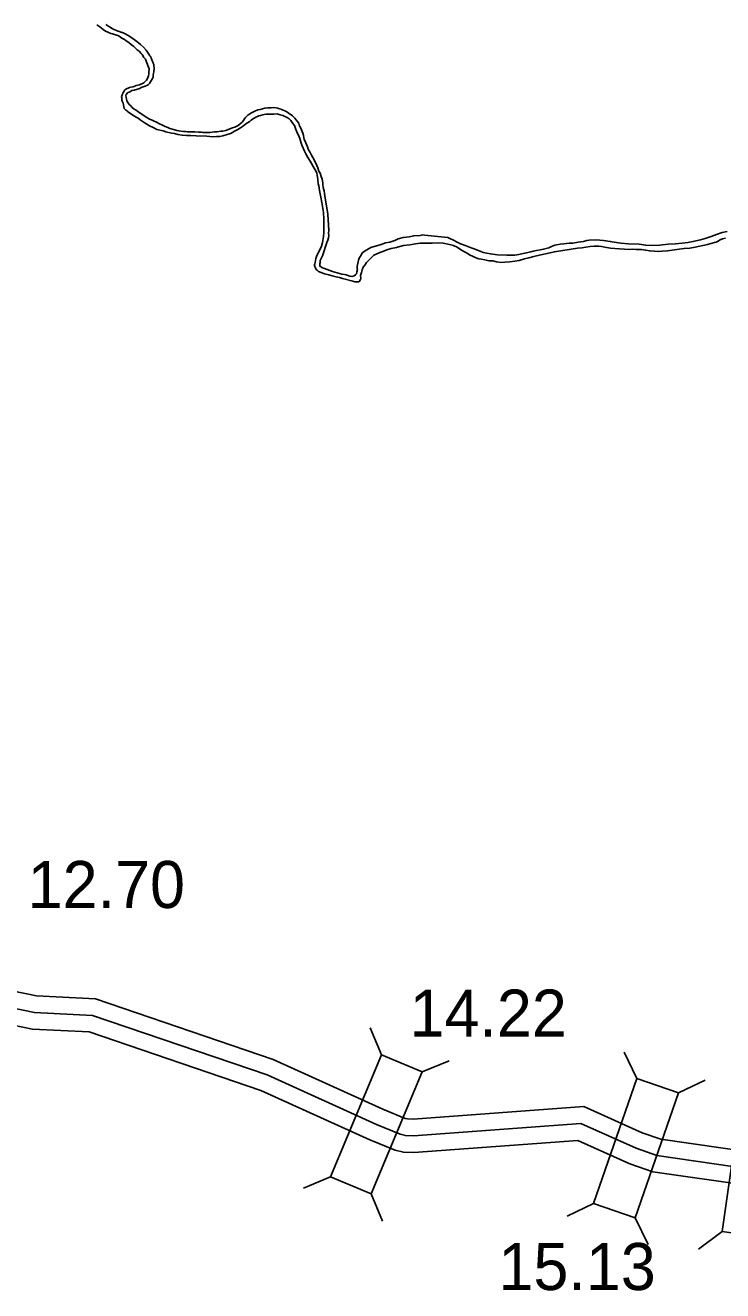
# Model space of a CAD drawing. Extents: x -83719 to 153526, y -11835 to 11446.
# Drawn here: x -2247.8 to -2038.9, y -454.1 to -75.2 of the extents above; entities that cross this region are included whole.
import ezdxf

# ---------------------------------------------------------------- set-up
doc = ezdxf.new("R2010")
doc.units = 0
for name, color, linetype in [('Level 10', 7, 'Continuous'), ('Level 20', 7, 'Continuous'), ('Level 25', 7, 'Continuous'), ('Level 58', 7, 'Continuous'), ('Level 59', 7, 'Continuous'), ('Level 9', 7, 'Continuous')]:
    doc.layers.add(name, color=color, linetype=linetype)

msp = doc.modelspace()

# ---------------------------------------------------------------- linework, layer by layer
at = {"layer": 'Level 10'}
for points in [[(-2375.71, -339.39), (-2328.82, -347.97), (-2266.83, -361.19), (-2244.37, -365.84), (-2226.7, -366.69), (-2173.53, -384.83), (-2140.64, -399.71), (-2134, -402.48), (-2133.29, -402.64), (-2131.62, -402.69), (-2080.47, -398.94), (-2063, -406.77), (-2057.47, -408.69), (-2029.08, -412.8), (-1988.92, -417.96), (-1987.26, -417.72), (-1985.49, -417.1), (-1983.44, -416.15), (-1964.63, -407.71), (-1915.1, -385.32), (-1891.4, -374.85)], [(-2379.18, -348.92), (-2330.76, -357.78), (-2268.89, -370.97), (-2245.63, -375.79), (-2228.59, -376.61), (-2177.21, -394.14), (-2144.62, -408.89), (-2137.04, -412.05), (-2134.54, -412.61), (-2131.41, -412.7), (-2082.26, -409.1), (-2066.69, -416.07), (-2059.85, -418.45), (-2030.43, -422.71), (-1988.85, -428.05), (-1984.86, -427.48), (-1981.74, -426.37), (-1979.31, -425.26), (-1960.53, -416.83), (-1911.02, -394.45), (-1887.36, -383.99)]]:
    msp.add_lwpolyline(points, dxfattribs=at)
at = {"layer": 'Level 20'}
for p, q in [((-2141.1, -383.49), (-2144.45, -375.35)), ((-2064.58, -390.55), (-2068.42, -382.63)), ((-2128.92, -388.56), (-2120.78, -385.22)), ((-2052.11, -394.89), (-2044.19, -391.05)), ((-2156.34, -420.04), (-2164.48, -423.39)), ((-2144.16, -425.12), (-2140.81, -433.25)), ((-2077.58, -427.96), (-2085.5, -431.79)), ((-2065.11, -432.29), (-2061.28, -440.21)), ((-2039.12, -436.41), (-2046.17, -441.67))]:
    msp.add_line(p, q, dxfattribs=at)
for points in [[(-2144.16, -425.12), (-2128.92, -388.56), (-2141.1, -383.49), (-2156.34, -420.04)], [(-2065.11, -432.29), (-2052.11, -394.89), (-2064.58, -390.55), (-2077.58, -427.96)], [(-2033.45, -397.21), (-2039.12, -436.41), (-2026.06, -438.3), (-2020.38, -399.1)]]:
    msp.add_lwpolyline(points, close=True, dxfattribs=at)
at = {"layer": 'Level 59'}
msp.add_lwpolyline([(-2267.86, -366.08), (-2245, -370.82), (-2227.65, -371.65), (-2175.37, -389.48), (-2142.63, -404.3), (-2135.52, -407.26), (-2133.91, -407.62), (-2131.51, -407.7), (-2081.36, -404.02), (-2064.85, -411.42), (-2058.66, -413.57), (-2029.75, -417.76), (-1988.88, -423.01), (-1986.06, -422.6), (-1983.61, -421.73), (-1981.37, -420.71), (-1962.58, -412.27), (-1913.06, -389.88), (-1889.38, -379.42)], dxfattribs=at)
at = {"layer": 'Level 9'}
for points in [[(-2215.06, -102.35), (-2217.02, -101.09), (-2217.19, -100.93), (-2217.77, -100.44), (-2218.11, -100.09), (-2218.26, -99.62), (-2218.31, -98.99), (-2218.49, -98.49), (-2218.59, -98.26), (-2218.73, -97.93), (-2218.81, -97.63), (-2218.85, -97.4), (-2218.89, -96.93), (-2218.93, -96.59), (-2218.87, -96.33), (-2218.78, -96.02), (-2218.69, -95.85), (-2218.5, -95.45), (-2218.3, -95.17), (-2218.08, -94.67), (-2217.95, -94.53), (-2217.66, -94.26), (-2216.54, -93.76), (-2216.2, -93.72), (-2215.44, -93.56), (-2214.55, -93.24), (-2213.59, -92.95), (-2213.36, -92.91), (-2212.63, -92.59), (-2212.24, -92.38), (-2211.49, -91.62), (-2211.23, -91.25), (-2210.82, -90.34), (-2210.8, -89.73), (-2210.81, -89.47), (-2210.72, -89), (-2210.66, -88.53), (-2210.67, -88.16), (-2211.53, -85.94), (-2211.81, -85.31), (-2212.22, -84.79), (-2212.78, -83.87), (-2213.02, -83.6), (-2213.67, -82.92), (-2214.25, -82.5), (-2214.93, -81.78), (-2215.27, -81.52), (-2215.95, -80.97), (-2216.8, -80.32), (-2217.55, -79.81), (-2218.09, -79.45), (-2218.83, -79), (-2219.65, -78.42), (-2220.05, -78.27), (-2221.03, -77.92), (-2221.6, -77.77), (-2222.1, -77.58), (-2223.05, -77.2), (-2223.72, -76.89), (-2224.43, -76.44), (-2225.45, -75.66), (-2226.3, -75.01)], [(-2218.66, -77.37), (-2218.88, -77.33), (-2219.62, -77.02), (-2220.29, -76.83), (-2221.16, -76.45), (-2221.64, -76.27), (-2222.04, -75.91), (-2222.59, -75.59), (-2222.99, -75.33), (-2223.6, -74.88)], [(-2218.66, -77.37), (-2217.83, -77.74), (-2216.96, -78.22), (-2215.87, -78.94), (-2214.37, -80.02), (-2213.23, -80.89), (-2212.36, -81.7), (-2211.58, -82.57), (-2210.72, -83.78)], [(-2210.53, -92.6), (-2209.67, -91.14), (-2209.44, -90.7), (-2209.43, -89.97), (-2209.37, -89.6), (-2209.29, -88.96), (-2209.17, -88.12), (-2209.3, -87.29), (-2209.31, -86.89), (-2209.45, -86.52), (-2209.77, -85.73), (-2209.91, -85.5), (-2210.09, -84.93), (-2210.26, -84.5), (-2210.47, -84.31), (-2210.72, -83.78)], [(-2171.91, -100.12), (-2172.14, -99.99), (-2173.12, -99.81), (-2174.08, -99.87), (-2174.41, -99.88), (-2175.08, -99.93), (-2175.98, -99.99), (-2176.71, -100.14), (-2177.44, -100.36), (-2178.1, -100.51), (-2179.02, -100.9), (-2179.98, -101.39), (-2180.54, -101.67), (-2181.09, -102.12), (-2181.81, -102.74), (-2182.1, -103.18), (-2182.42, -103.69), (-2182.81, -104.17), (-2183.43, -104.72), (-2184.05, -105.14), (-2185.04, -105.63), (-2185.7, -105.92), (-2186.49, -106.2), (-2187.72, -106.64), (-2188.61, -106.83), (-2189.18, -106.91), (-2190.3, -107.07), (-2191.1, -107.09), (-2191.8, -107.18), (-2192.43, -107.22), (-2193.17, -107.24), (-2193.87, -107.29), (-2194.57, -107.25), (-2195.04, -107.19), (-2195.87, -107.14), (-2196.94, -107.07), (-2197.54, -107.05), (-2199.24, -107.03), (-2199.64, -107.01), (-2200.38, -106.92), (-2201.18, -106.84), (-2201.81, -106.76), (-2202.35, -106.64), (-2202.99, -106.52), (-2204.47, -106.03), (-2205.07, -105.77), (-2205.88, -105.49), (-2206.45, -105.21), (-2207.8, -104.57), (-2208.48, -104.22), (-2209.12, -103.87), (-2209.93, -103.52), (-2210.6, -103.27), (-2211.55, -102.66), (-2212.26, -102.21), (-2213.31, -101.47), (-2214.02, -101.02), (-2214.6, -100.63), (-2215.14, -100.28), (-2215.72, -99.82), (-2216.2, -99.33), (-2216.68, -98.88), (-2217.27, -97.99), (-2217.37, -97.73), (-2217.48, -97.26), (-2217.53, -96.73), (-2217.67, -96.33), (-2217.52, -95.92), (-2217.13, -95.38), (-2216.27, -94.96), (-2215.81, -94.68), (-2215.15, -94.59), (-2213.46, -94.08), (-2213.03, -93.8), (-2212.11, -93.48), (-2211.38, -93.16), (-2210.99, -92.95), (-2210.53, -92.6)], [(-2158.15, -149.62), (-2160, -148.94), (-2160.28, -148.64), (-2160.55, -148.38), (-2160.76, -148.09), (-2160.97, -147.59), (-2161.04, -147.39), (-2161.18, -147.09), (-2161.19, -146.86), (-2161.09, -146.56), (-2160.97, -146.15), (-2160.89, -145.55), (-2160.8, -144.98), (-2160.42, -144.1), (-2159.78, -142.84), (-2159.09, -141.32), (-2158.72, -140.24), (-2158.46, -138.43), (-2158.39, -137.23), (-2158.32, -134.85), (-2158.32, -133.18), (-2158.5, -131.24), (-2158.75, -129.44), (-2158.98, -128.21), (-2159.22, -126.68), (-2159.63, -124.62), (-2159.9, -123.25), (-2160.05, -122.69), (-2160.12, -121.29), (-2160.31, -120.15), (-2160.46, -119.39), (-2160.95, -118.46), (-2161.51, -117.41), (-2162.1, -116.55), (-2162.48, -115.89), (-2163.18, -114.71), (-2163.71, -113.62), (-2164.12, -112.89), (-2164.87, -111.24), (-2165.15, -110.45), (-2165.59, -109.09), (-2165.91, -108.06), (-2166.4, -107.17), (-2166.93, -105.78), (-2167.18, -105.18), (-2167.6, -104.56), (-2168.22, -103.63), (-2168.73, -103.21), (-2169.37, -102.79), (-2169.81, -102.61), (-2170.62, -102.22), (-2171.43, -101.94), (-2172.34, -101.67), (-2173.37, -101.73), (-2174.13, -101.81), (-2174.83, -101.8), (-2175.6, -101.78), (-2176.26, -101.9), (-2176.63, -101.94), (-2177.36, -102.13), (-2177.79, -102.27), (-2178.22, -102.45), (-2178.71, -102.7), (-2179.01, -102.91), (-2179.4, -103.05), (-2180.16, -103.6), (-2180.51, -103.95), (-2181.44, -104.44), (-2182.74, -105.44), (-2183.33, -105.89), (-2184.15, -106.41), (-2185.27, -106.98), (-2186.03, -107.46), (-2186.59, -107.68), (-2187.28, -107.9), (-2188.58, -108.26), (-2189.47, -108.42), (-2190.47, -108.51), (-2191.57, -108.57), (-2193.44, -108.39), (-2196.54, -108.27), (-2198.18, -108.14), (-2199.51, -108.21), (-2200.78, -108.04), (-2202.09, -107.87), (-2203.09, -107.56), (-2203.93, -107.45), (-2205.64, -107.02), (-2206.48, -106.78), (-2208.32, -106.36), (-2209.47, -105.78), (-2210.59, -105.24), (-2212.18, -104.31), (-2213.4, -103.44), (-2213.94, -103.02), (-2214.52, -102.67), (-2215.06, -102.35)], [(-2168.93, -101.48), (-2169.04, -101.42), (-2169.48, -101.09), (-2170.03, -100.74), (-2170.56, -100.55), (-2171.2, -100.33), (-2171.91, -100.12)], [(-2168.93, -101.48), (-2168.41, -101.77), (-2167.75, -102.31), (-2167.03, -103), (-2166.43, -103.76), (-2165.89, -104.51), (-2165.65, -105.32), (-2165.29, -106.01), (-2164.84, -106.94), (-2164.63, -107.48), (-2164.45, -108.17), (-2164.2, -109.35)], [(-2103.58, -143.96), (-2106.35, -143.9), (-2108.46, -143.65), (-2110.67, -143.17), (-2111.58, -142.83), (-2112.66, -142.42), (-2113.36, -142.1), (-2114.21, -141.79), (-2115.72, -141.23), (-2116.86, -140.82), (-2117.47, -140.57), (-2118.41, -140.12), (-2119.53, -139.48), (-2120.61, -139.04), (-2121.25, -138.76), (-2128.23, -137.97), (-2128.67, -137.94), (-2129.53, -138.1), (-2131.43, -138.18), (-2132.82, -138.52), (-2134.58, -138.69), (-2136.11, -139.1), (-2137.06, -139.56), (-2138.62, -140.1), (-2139.91, -140.27), (-2141.2, -140.8), (-2144.28, -141.75), (-2145.46, -142.41), (-2146.84, -143.32), (-2147.22, -143.96), (-2147.73, -144.88), (-2148.02, -145.46), (-2148.37, -147.4), (-2148.36, -147.97), (-2148.31, -148.34), (-2148.5, -148.95), (-2148.62, -149.62), (-2148.88, -149.89), (-2149.27, -150.2), (-2149.97, -150.35), (-2150.53, -150.27), (-2151.64, -149.93), (-2152.14, -149.84), (-2153.01, -149.73), (-2155.8, -148.86), (-2158.19, -147.99), (-2158.8, -147.77), (-2159.27, -147.51), (-2159.34, -147.48), (-2159.51, -147.18), (-2159.58, -146.92), (-2159.55, -146.85), (-2159.56, -146.48), (-2159.5, -146.21), (-2159.45, -145.61), (-2159.23, -145.2), (-2158.72, -144.19), (-2157.42, -140.21), (-2157.13, -139.53), (-2156.95, -138.79), (-2156.9, -138.16), (-2156.95, -137.46), (-2156.87, -136.62), (-2157.19, -131.68), (-2158.06, -126.28), (-2158.18, -125.58), (-2158.26, -124.75), (-2158.52, -123.75), (-2158.61, -122.95), (-2158.69, -122.35), (-2158.82, -121.25), (-2159.21, -120.16), (-2159.46, -119.4), (-2159.81, -118.87), (-2160.13, -117.88), (-2160.49, -117.15), (-2161.05, -115.89), (-2161.64, -114.8), (-2162.1, -114.05), (-2162.48, -113.29), (-2163.04, -112.3), (-2163.29, -111.53), (-2163.58, -110.84), (-2163.89, -110.21), (-2164.07, -109.62), (-2164.2, -109.35)], [(-2037.62, -136.9), (-2039.08, -137.24), (-2040.73, -137.82), (-2042.38, -138.4), (-2044.13, -138.98), (-2045.56, -139.38), (-2047.81, -139.94), (-2049.34, -140.24), (-2051.1, -140.39), (-2053.09, -140.64), (-2055.26, -140.73), (-2057.72, -140.99), (-2060.05, -141.08), (-2061.98, -141.03), (-2063.96, -140.68), (-2067.16, -140.6), (-2069.43, -140.42), (-2071.38, -140.1), (-2072.58, -139.9), (-2074.66, -139.58), (-2076.76, -139.43), (-2078.86, -139.49), (-2079.62, -139.64), (-2080.58, -139.87), (-2082.24, -140.11), (-2083.84, -140.38), (-2084.87, -140.41), (-2086.53, -140.59), (-2087.63, -140.75), (-2089.15, -141.05), (-2090.18, -141.41), (-2090.97, -141.77), (-2092.56, -142.24), (-2095.64, -142.82), (-2096.41, -142.98), (-2097.73, -143.31), (-2099.92, -143.77), (-2101.12, -144), (-2102.48, -144.03), (-2103.58, -143.96)], [(-2038.07, -138.89), (-2038.96, -139.08), (-2039.65, -139.43), (-2040.44, -139.88), (-2040.9, -140.13), (-2041.37, -140.24)], [(-2041.37, -140.24), (-2042.03, -140.43), (-2043.42, -140.76), (-2047.2, -141.63), (-2048.73, -141.87), (-2050.42, -142.04), (-2051.99, -142.18), (-2054.05, -142.47), (-2055.41, -142.67), (-2057.01, -142.85), (-2058.17, -142.88), (-2059.31, -142.77), (-2060.78, -142.71), (-2062.02, -142.47), (-2063.22, -142.34), (-2064.79, -142.27), (-2065.79, -142.23), (-2066.92, -142.26), (-2068.36, -142.23), (-2069.82, -142.13), (-2071.2, -141.97), (-2072.47, -141.87), (-2073.74, -141.67), (-2075.24, -141.37), (-2075.98, -141.29), (-2077.38, -141.32), (-2078.64, -141.42), (-2079.91, -141.59), (-2081.13, -141.79), (-2082.43, -141.92), (-2089.31, -142.96), (-2090.63, -143.3), (-2091.99, -143.6), (-2093.35, -143.87), (-2095.47, -144.36), (-2096.96, -144.76), (-2098.25, -145.13), (-2099.84, -145.57), (-2101.14, -145.77), (-2102.7, -146.04), (-2104.17, -146.05), (-2105.36, -146.21), (-2106.67, -146.01), (-2107.71, -145.74), (-2108.94, -145.7), (-2110.15, -145.43), (-2111.25, -145.23), (-2111.92, -145.11), (-2112.53, -144.89), (-2114.69, -143.87), (-2115.43, -143.43), (-2116.41, -142.88), (-2117.39, -142.34), (-2118.41, -141.63), (-2119.56, -141.12), (-2120.73, -140.82), (-2122.61, -140.43), (-2123.88, -140.33), (-2125.91, -140.38), (-2127.41, -140.42), (-2129.51, -140.44), (-2130.94, -140.64), (-2132.56, -140.88), (-2134.46, -141.13), (-2135.62, -141.4), (-2136.64, -141.66), (-2138.24, -142), (-2139.49, -142.43), (-2140.68, -142.86), (-2141.57, -143.22), (-2142.69, -143.75), (-2143.35, -144.03), (-2143.81, -144.38), (-2144.23, -144.82), (-2144.56, -145.17), (-2145.63, -146.2), (-2146.08, -146.98), (-2146.6, -147.63), (-2146.88, -148.4), (-2147.03, -149.18), (-2147.34, -150.12), (-2147.29, -150.85), (-2147.34, -151.29), (-2147.63, -151.8), (-2147.99, -151.94), (-2148.42, -151.99), (-2149.06, -151.97), (-2149.63, -151.82), (-2152.75, -150.96), (-2153.66, -150.71), (-2154.7, -150.51), (-2155.87, -150.24), (-2156.88, -149.93), (-2158.15, -149.62)]]:
    msp.add_lwpolyline(points, dxfattribs=at)

# ---------------------------------------------------------------- texts
at = {"layer": 'Level 25'}
msp.add_text('14.22', height=14.08, dxfattribs=at).set_placement((-2132.71, -378))
at = {"layer": 'Level 58'}
for s, p in [('12.70', (-2247.05, -339.49)), ('14.22', (-2132.71, -378)), ('15.13', (-2106.07, -453.89))]:
    msp.add_text(s, height=14.08, dxfattribs=at).set_placement(p)

doc.saveas('drawing.dxf')
